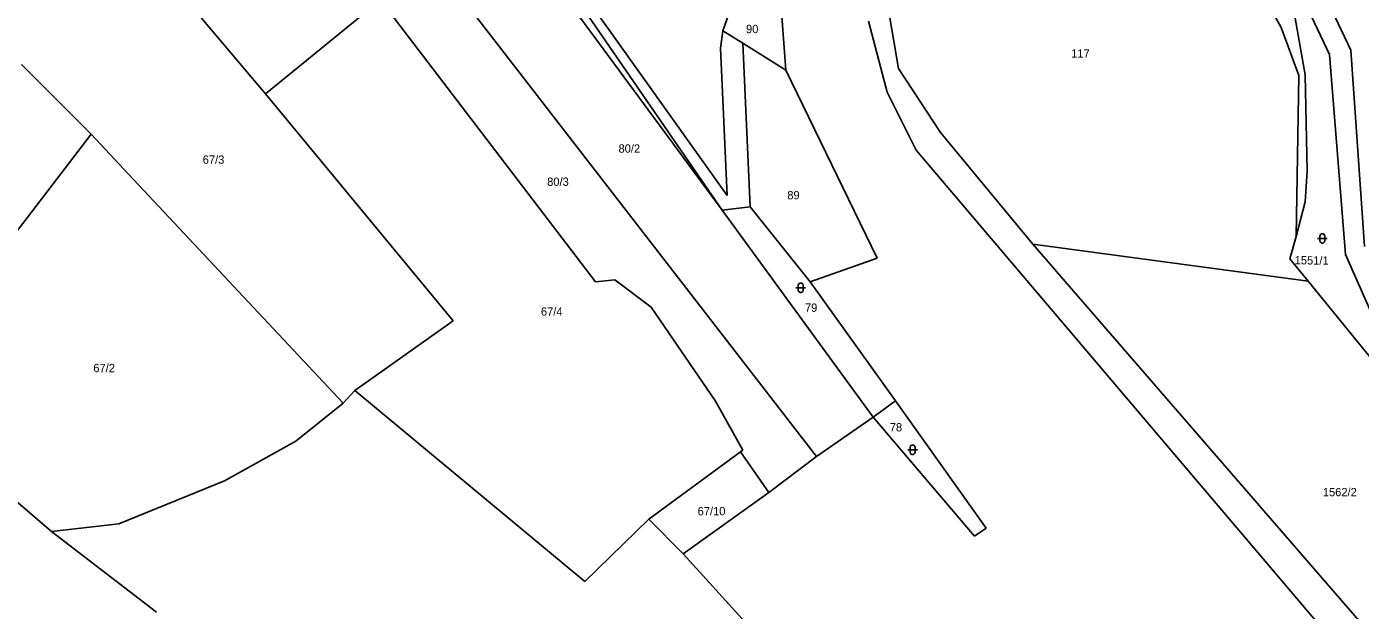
# Model space of a CAD drawing. Extents: x -799786 to -795190, y -1021716 to -1017834.
# Drawn here: x -797930.9 to -797657.9, y -1019260.7 to -1019141.2 of the extents above; entities that cross this region are included whole.
import ezdxf

# ---------------------------------------------------------------- set-up
doc = ezdxf.new("R2010")
doc.units = 0
for name, color, linetype in [('Default', 7, 'Continuous'), ('KN_HRANICE', 7, 'Continuous'), ('KN_KULTURY', 7, 'Continuous'), ('KN_PARCELY', 7, 'Continuous')]:
    doc.layers.add(name, color=color, linetype=linetype)

# ---------------------------------------------------------------- blocks, each defined once
blk = doc.blocks.new('316')
at = {"layer": 'Default'}
for points in [[(-1, 1), (0.27, 1), (1, 1)], [(-0.5, 1.5), (-0.4, 1.79), (-0.15, 1.97), (0.16, 1.97), (0.41, 1.79), (0.51, 1.5), (0.51, 0.5), (0.41, 0.21), (0.16, 0.03), (-0.15, 0.03), (-0.4, 0.21), (-0.5, 0.5), (-0.5, 1.5)]]:
    blk.add_lwpolyline(points, dxfattribs=at)

msp = doc.modelspace()

# ---------------------------------------------------------------- linework, layer by layer
at = {"layer": 'KN_HRANICE'}
for p, q in [((-797659.88, -1019146), (-797680.85, -1019101.69)), ((-797664.24, -1019146.89), (-797682.36, -1019108.61)), ((-797691.05, -1019110.67), (-797674.12, -1019141.38)), ((-797853.47, -1019120.29), (-797769.25, -1019229.18)), ((-797826.91, -1019123.02), (-797788.58, -1019178.77)), ((-797783.1, -1019126.77), (-797788.38, -1019142.03)), ((-797787.5, -1019175.75), (-797820.48, -1019129.46)), ((-797788.58, -1019178.77), (-797821.92, -1019133.49)), ((-797881.99, -1019154.95), (-797858.44, -1019135.72)), ((-797814.48, -1019193.44), (-797858.44, -1019135.72)), ((-797881.99, -1019154.95), (-797895.08, -1019139.44)), ((-797775.5, -1019150.13), (-797776.38, -1019138.19)), ((-797754.62, -1019137), (-797752.49, -1019149.73)), ((-797788.38, -1019142.03), (-797788.92, -1019145.61)), ((-797784.32, -1019144.6), (-797788.38, -1019142.03)), ((-797758.63, -1019140.07), (-797754.77, -1019154.63)), ((-797674.12, -1019141.38), (-797670.56, -1019151.16)), ((-797784.32, -1019144.6), (-797775.5, -1019150.13)), ((-797782.84, -1019178.1), (-797784.32, -1019144.6)), ((-797788.92, -1019145.61), (-797787.5, -1019175.75)), ((-797660.98, -1019187.84), (-797664.24, -1019146.89)), ((-797657.11, -1019186.19), (-797659.88, -1019146)), ((-797931.93, -1019148.94), (-797917.67, -1019163.19)), ((-797756.8, -1019188.61), (-797775.5, -1019150.13)), ((-797752.49, -1019149.73), (-797743.89, -1019162.83)), ((-797670.56, -1019151.16), (-797671.05, -1019184.15)), ((-797881.99, -1019154.95), (-797843.57, -1019201.42)), ((-797754.77, -1019154.63), (-797748.84, -1019166.49)), ((-797958.45, -1019216.47), (-797917.67, -1019163.19)), ((-797917.67, -1019163.19), (-797911.03, -1019170.39)), ((-797743.89, -1019162.83), (-797724.98, -1019185.71)), ((-797748.84, -1019166.49), (-797606.89, -1019333.62)), ((-797911.03, -1019170.39), (-797866.12, -1019218.23)), ((-797788.58, -1019178.77), (-797782.84, -1019178.1)), ((-797757.63, -1019221.13), (-797788.58, -1019178.77)), ((-797782.84, -1019178.1), (-797770.51, -1019193.4)), ((-797724.98, -1019185.71), (-797632.85, -1019292.08)), ((-797724.98, -1019185.71), (-797668.59, -1019193.31)), ((-797671.05, -1019184.15), (-797672.34, -1019188.7)), ((-797770.51, -1019193.4), (-797756.8, -1019188.61)), ((-797672.34, -1019188.7), (-797668.59, -1019193.31)), ((-797652.26, -1019207.55), (-797660.98, -1019187.84)), ((-797810.52, -1019193.04), (-797814.48, -1019193.44)), ((-797803.09, -1019198.62), (-797810.52, -1019193.04)), ((-797753.1, -1019217.82), (-797770.51, -1019193.4)), ((-797668.59, -1019193.31), (-797646.53, -1019220.44)), ((-797789.88, -1019217.83), (-797803.09, -1019198.62)), ((-797863.75, -1019215.64), (-797843.57, -1019201.42)), ((-797866.12, -1019218.23), (-797863.75, -1019215.64)), ((-797863.75, -1019215.64), (-797816.63, -1019254.77)), ((-797866.12, -1019218.23), (-797875.8, -1019226.01)), ((-797784.34, -1019227.86), (-797789.88, -1019217.83)), ((-797753.1, -1019217.82), (-797757.63, -1019221.13)), ((-797734.53, -1019243.84), (-797753.1, -1019217.82)), ((-797769.25, -1019229.18), (-797757.63, -1019221.13)), ((-797757.63, -1019221.13), (-797736.89, -1019245.46)), ((-797875.8, -1019226.01), (-797890.42, -1019234.13)), ((-797946.01, -1019227.17), (-797925.82, -1019244.54)), ((-797784.79, -1019228.2), (-797803.56, -1019241.99)), ((-797784.79, -1019228.2), (-797784.34, -1019227.86)), ((-797779.01, -1019236.54), (-797784.79, -1019228.2)), ((-797779.01, -1019236.54), (-797769.25, -1019229.18)), ((-797890.42, -1019234.13), (-797912.02, -1019242.95)), ((-797796.53, -1019249.12), (-797779.01, -1019236.54)), ((-797912.02, -1019242.95), (-797925.82, -1019244.54)), ((-797816.63, -1019254.77), (-797803.56, -1019241.99)), ((-797803.56, -1019241.99), (-797796.53, -1019249.12)), ((-797904.34, -1019261.03), (-797925.82, -1019244.54)), ((-797736.89, -1019245.46), (-797734.53, -1019243.84)), ((-797796.53, -1019249.12), (-797761.01, -1019288.16))]:
    msp.add_line(p, q, dxfattribs=at)
msp.add_lwpolyline([(-797671.05, -1019184.15), (-797669.23, -1019177.06), (-797668.82, -1019170.8), (-797669.25, -1019151.05), (-797671.49, -1019138.3), (-797673.31, -1019132.02), (-797682.36, -1019108.61)], dxfattribs=at)

# ---------------------------------------------------------------- block references
at = {"layer": 'KN_KULTURY'}
for p in [(-797665.73, -1019185.55), (-797772.46, -1019195.64), (-797749.57, -1019228.8)]:
    msp.add_blockref('316', p, dxfattribs=at)

# ---------------------------------------------------------------- texts
at = {"layer": 'KN_PARCELY'}
for s, p in [('90', (-797783.67, -1019142.52)), ('117', (-797717.12, -1019147.53)), ('80/2', (-797809.76, -1019166.99)), ('67/3', (-797894.85, -1019169.26)), ('80/3', (-797824.36, -1019173.78)), ('89', (-797775.22, -1019176.53)), ('67/4', (-797825.64, -1019200.36)), ('79', (-797771.6, -1019199.56)), ('67/2', (-797917.24, -1019211.92)), ('78', (-797754.25, -1019224.05)), ('1562/2', (-797665.62, -1019237.32)), ('67/10', (-797793.57, -1019241.22))]:
    msp.add_text(s, height=1.7, dxfattribs=at).set_placement(p)
msp.add_text('1551/1', height=1.7, rotation=359.302, dxfattribs=at).set_placement((-797671.39, -1019189.84))

doc.saveas('drawing.dxf')
